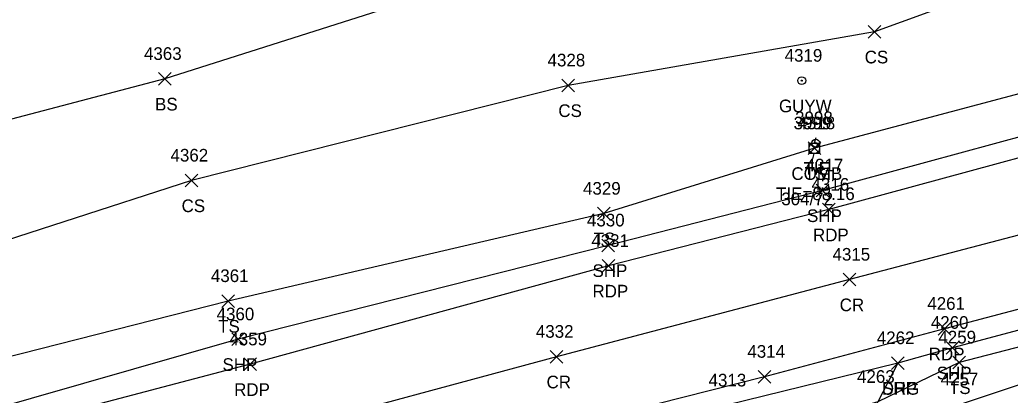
# Model space of a CAD drawing. Extents: x 1520648 to 1523413, y 732854 to 735518.
# Drawn here: x 1520739.3 to 1520895.7, y 733427.6 to 733487 of the extents above; entities that cross this region are included whole.
import ezdxf

# ---------------------------------------------------------------- set-up
doc = ezdxf.new("R2010")
doc.units = 0
for name, color, linetype in [('C_A', 7, 'Continuous'), ('C_C', 7, 'Continuous'), ('C_I', 7, 'Continuous'), ('CBP', 7, 'Continuous'), ('L_A', 7, 'Continuous'), ('L_I', 7, 'Continuous'), ('L_TIC', 7, 'Continuous'), ('LELB', 7, 'Continuous'), ('P_A', 7, 'Continuous'), ('P_I', 7, 'Continuous'), ('P_TIC', 7, 'Continuous'), ('PET', 7, 'Continuous'), ('PRC', 7, 'Continuous'), ('PSP', 7, 'Continuous'), ('R_A', 7, 'Continuous'), ('R_I', 7, 'Continuous'), ('R_TIC', 7, 'Continuous'), ('RDG', 7, 'Continuous'), ('U_A', 7, 'Continuous'), ('U_C', 7, 'Continuous'), ('U_I', 7, 'Continuous'), ('UP', 7, 'Continuous'), ('UPGW', 7, 'Continuous')]:
    doc.layers.add(name, color=color, linetype=linetype)

msp = doc.modelspace()

# ---------------------------------------------------------------- linework, layer by layer
at = {"layer": 'CBP'}
for radius in [0.625, 0.0833]:
    msp.add_circle((1520864.99, 733467.49), radius, dxfattribs=at)
at = {"layer": 'L_TIC'}
for points in [[(1520873.27, 733484.11), (1520875.27, 733486.11)], [(1520875.27, 733484.11), (1520873.27, 733486.11)], [(1520761.19, 733476.66), (1520763.19, 733478.66)], [(1520763.19, 733476.66), (1520761.19, 733478.66)], [(1520824.89, 733475.63), (1520826.89, 733477.63)], [(1520826.89, 733475.63), (1520824.89, 733477.63)], [(1520863.8, 733465.7), (1520865.8, 733467.7)], [(1520865.8, 733465.7), (1520863.8, 733467.7)], [(1520765.38, 733460.59), (1520767.38, 733462.59)], [(1520767.38, 733460.59), (1520765.38, 733462.59)], [(1520830.5, 733455.35), (1520832.5, 733457.35)], [(1520832.5, 733455.35), (1520830.5, 733457.35)], [(1520771.19, 733441.53), (1520773.19, 733443.53)], [(1520773.19, 733441.53), (1520771.19, 733443.53)], [(1520886.62, 733431.82), (1520888.62, 733433.82)], [(1520888.62, 733431.82), (1520886.62, 733433.82)]]:
    msp.add_lwpolyline(points, dxfattribs=at)
at = {"layer": 'LELB'}
for points in [[(1520933.58, 733575.42), (1520942.19, 733540.15), (1520944.3, 733517.3), (1520942.35, 733502.31), (1520935.92, 733493.43), (1520920.42, 733481.51), (1520864.8, 733466.7), (1520831.5, 733456.35), (1520772.19, 733442.53), (1520730.55, 733431.91), (1520670.98, 733415.63)], [(1520924.94, 733571.69), (1520931.25, 733539.14), (1520932.11, 733517.28), (1520920.03, 733501.75), (1520874.27, 733485.11), (1520825.89, 733476.63), (1520766.38, 733461.59), (1520726.01, 733448.53), (1520664.21, 733429.23)], [(1520912.95, 733567.21), (1520918.33, 733540.81), (1520912.15, 733526.62), (1520872.04, 733499.31), (1520820.67, 733496.33), (1520762.19, 733477.66), (1520720.67, 733466.78), (1520660.6, 733449.58)], [(1521084, 733484.54), (1521067.58, 733479.07), (1521049.77, 733473.83), (1520986.71, 733459.8), (1520946.37, 733448.2), (1520906.56, 733437.71), (1520887.62, 733432.82), (1520874.82, 733426.59), (1520851.23, 733419.6), (1520833.59, 733418.06), (1520824.1, 733415.79), (1520817.47, 733414.55), (1520789.23, 733404.3), (1520782.06, 733399.14), (1520771.54, 733396.06), (1520749.1, 733390.85), (1520744.37, 733386.94), (1520745.44, 733378.48), (1520749.8, 733369.39), (1520752.39, 733361.75), (1520762.08, 733336.81), (1520765.3, 733336.98)], [(1521038.84, 733468.84), (1520987.4, 733455.86), (1520949.31, 733443.39), (1520907.36, 733432.7), (1520887.97, 733426.2), (1520871.27, 733419.86), (1520861.99, 733407.36), (1520847.71, 733403.77), (1520838.35, 733404.94), (1520822.18, 733406.09), (1520819.36, 733394.56), (1520817.03, 733387.06)]]:
    msp.add_lwpolyline(points, dxfattribs=at)
at = {"layer": 'P_TIC'}
for points in [[(1520865.08, 733459.02), (1520867.08, 733461.02)], [(1520867.08, 733459.02), (1520865.08, 733461.02)], [(1520866.06, 733455.98), (1520868.06, 733457.98)], [(1520868.06, 733455.98), (1520866.06, 733457.98)], [(1520831.2, 733450.33), (1520833.2, 733452.33)], [(1520833.2, 733450.33), (1520831.2, 733452.33)], [(1520831.23, 733447.09), (1520833.23, 733449.09)], [(1520833.23, 733447.09), (1520831.23, 733449.09)], [(1520869.34, 733444.92), (1520871.34, 733446.92)], [(1520871.34, 733444.92), (1520869.34, 733446.92)], [(1520884.35, 733437.14), (1520886.35, 733439.14)], [(1520886.35, 733437.14), (1520884.35, 733439.14)], [(1520772.75, 733435.48), (1520774.75, 733437.48)], [(1520774.75, 733435.48), (1520772.75, 733437.48)], [(1520885.57, 733434.14), (1520887.57, 733436.14)], [(1520887.57, 733434.14), (1520885.57, 733436.14)], [(1520823.04, 733432.72), (1520825.04, 733434.72)], [(1520825.04, 733432.72), (1520823.04, 733434.72)], [(1520774.63, 733431.52), (1520776.63, 733433.52)], [(1520776.63, 733431.52), (1520774.63, 733433.52)], [(1520876.93, 733431.71), (1520878.93, 733433.71)], [(1520878.93, 733431.71), (1520876.93, 733433.71)], [(1520855.88, 733429.56), (1520857.88, 733431.56)], [(1520857.88, 733429.56), (1520855.88, 733431.56)]]:
    msp.add_lwpolyline(points, dxfattribs=at)
at = {"layer": 'PET'}
for points in [[(1521359.51, 733585.39), (1521298.08, 733569.34), (1521228.86, 733551.45), (1521196.2, 733542.53), (1521147.39, 733530.28), (1521096.51, 733517.17), (1521058.61, 733507.66), (1520970.9, 733484.81), (1520924.79, 733472.7), (1520867.06, 733456.98), (1520832.23, 733448.09), (1520775.63, 733432.52), (1520733.45, 733421.44), (1520673.24, 733405.46)], [(1521365.83, 733563.19), (1521305.64, 733547.24), (1521243.51, 733531.59), (1521203.56, 733520.88), (1521152.14, 733507.85), (1521105.31, 733495.85), (1521097.86, 733494.19), (1521063.42, 733485.34), (1521018.35, 733473.43), (1520975.95, 733462.3), (1520931.61, 733450.37), (1520885.35, 733438.14), (1520856.88, 733430.56), (1520818.39, 733420.77), (1520780.83, 733410.61), (1520744.81, 733401.09), (1520678.56, 733383.16)]]:
    msp.add_lwpolyline(points, dxfattribs=at)
at = {"layer": 'PRC'}
msp.add_lwpolyline([(1521363.3, 733574.52), (1521301.52, 733558.53), (1521239.8, 733542.16), (1521200.1, 733531.63), (1521149.34, 733518.97), (1521098.13, 733505.5), (1521061.28, 733496.8), (1521014.81, 733484.07), (1520973.92, 733473.61), (1520928.9, 733461.35), (1520870.34, 733445.92), (1520824.04, 733433.72), (1520778.39, 733421.36), (1520737.02, 733410.36), (1520676.97, 733394.51)], dxfattribs=at)
at = {"layer": 'PSP'}
for points in [[(1521358.34, 733588.53), (1521296.5, 733572.12), (1521227.74, 733554.37), (1521195.21, 733545.64), (1521147.51, 733533.73), (1521095.86, 733520.25), (1521076.01, 733514.97), (1521056.93, 733511.88), (1521033.51, 733506.4), (1520966.21, 733488.2), (1520925.69, 733476.27), (1520866.08, 733460.02), (1520832.2, 733451.33), (1520773.75, 733436.48), (1520732.76, 733424.74), (1520671.96, 733408.83)], [(1521366.85, 733559.74), (1521307.16, 733544.25), (1521244.3, 733528.24), (1521204.94, 733517.79), (1521152.82, 733504.37), (1521106.57, 733492.89), (1521080.1, 733485.88), (1521063.46, 733481.98), (1521018.86, 733470.55), (1520976.52, 733459.1), (1520931.66, 733447.13), (1520886.57, 733435.14), (1520877.93, 733432.71), (1520850.75, 733426.02), (1520817.82, 733417.13), (1520781.5, 733407.41), (1520747.69, 733397.94), (1520743.14, 733395.11), (1520720.82, 733389.47), (1520716.87, 733390.02), (1520705.4, 733386.95), (1520679.31, 733380.34)]]:
    msp.add_lwpolyline(points, dxfattribs=at)
at = {"layer": 'R_TIC'}
for points in [[(1520876.93, 733431.71), (1520878.93, 733433.71)], [(1520878.93, 733431.71), (1520876.93, 733433.71)]]:
    msp.add_lwpolyline(points, dxfattribs=at)
at = {"layer": 'RDG'}
msp.add_lwpolyline([(1520877.93, 733432.71), (1520874.82, 733426.59), (1520871.27, 733419.86), (1520872.04, 733411.55), (1520882.83, 733406.82), (1520886.47, 733392.68), (1520888.14, 733371.18), (1520869.05, 733363.96), (1520863.07, 733360.43), (1520863.54, 733349.73)], dxfattribs=at)
at = {"layer": 'UP'}
for p, q in [((1520863.93, 733465.84), (1520863.93, 733467.51)), ((1520863.93, 733467.51), (1520865.6, 733467.51)), ((1520865.01, 733468.34), (1520864.76, 733467.51)), ((1520865.6, 733467.51), (1520865.6, 733465.84)), ((1520865.6, 733465.84), (1520863.93, 733465.84)), ((1520864.51, 733465.01), (1520864.76, 733465.84)), ((1520864.76, 733466.68), (1520864.76, 733466.68))]:
    msp.add_line(p, q, dxfattribs=at)
msp.add_circle((1520864.76, 733466.68), 0.833, dxfattribs=at)
at = {"layer": 'UPGW'}
for radius in [0.625, 0.0833]:
    msp.add_circle((1520862.78, 733477.38), radius, dxfattribs=at)

# ---------------------------------------------------------------- texts
at = {"layer": 'C_A'}
msp.add_text('TIE', height=2, dxfattribs=at).set_placement((1520863.07, 733462.49))
at = {"layer": 'C_C'}
msp.add_text('TIE=88.16', height=2, dxfattribs=at).set_placement((1520858.73, 733458.49))
at = {"layer": 'C_I'}
msp.add_text('3998', height=2, dxfattribs=at).set_placement((1520861.73, 733470.49))
at = {"layer": 'L_A'}
for s, p in [('CS', (1520872.72, 733480.11)), ('BS', (1520760.63, 733472.66)), ('CS', (1520824.33, 733471.63)), ('TS', (1520863.21, 733461.7)), ('CS', (1520764.82, 733456.59)), ('TS', (1520829.91, 733451.35)), ('TS', (1520770.6, 733437.53)), ('TS', (1520886.03, 733427.82))]:
    msp.add_text(s, height=2, dxfattribs=at).set_placement(p)
at = {"layer": 'L_I'}
for s, p in [('4363', (1520758.88, 733480.66)), ('4328', (1520822.63, 733479.63)), ('4318', (1520862.11, 733469.7)), ('4362', (1520763.07, 733464.59)), ('4329', (1520828.23, 733459.35)), ('4361', (1520769.45, 733445.53)), ('4259', (1520884.36, 733435.82)), ('4263', (1520871.51, 733429.59)), ('4257', (1520884.72, 733429.2))]:
    msp.add_text(s, height=2, dxfattribs=at).set_placement(p)
at = {"layer": 'P_A'}
for s, p in [('SHP', (1520863.61, 733455.02)), ('RDP', (1520864.55, 733451.98)), ('SHP', (1520829.73, 733446.33)), ('RDP', (1520829.72, 733443.09)), ('CR', (1520868.77, 733440.92)), ('RDP', (1520882.84, 733433.14)), ('SHP', (1520771.28, 733431.48)), ('SHP', (1520884.1, 733430.14)), ('CR', (1520822.47, 733428.72)), ('RDP', (1520773.12, 733427.52)), ('SHP', (1520875.47, 733427.71))]:
    msp.add_text(s, height=2, dxfattribs=at).set_placement(p)
at = {"layer": 'P_I'}
for s, p in [('4317', (1520863.39, 733463.02)), ('4316', (1520864.32, 733459.98)), ('4330', (1520828.85, 733454.33)), ('4331', (1520829.54, 733451.09)), ('4315', (1520867.64, 733448.92)), ('4261', (1520882.61, 733441.14)), ('4360', (1520770.35, 733439.48)), ('4260', (1520883.17, 733438.14)), ('4332', (1520820.78, 733436.72)), ('4262', (1520874.63, 733435.71)), ('4359', (1520772.36, 733435.52)), ('4314', (1520854.19, 733433.56)), ('4313', (1520848.06, 733429.02))]:
    msp.add_text(s, height=2, dxfattribs=at).set_placement(p)
at = {"layer": 'R_A'}
msp.add_text('DRG', height=2, dxfattribs=at).set_placement((1520875.42, 733427.71))
at = {"layer": 'R_I'}
for s, p in [('4262', (1520874.63, 733435.71)), ('4263', (1520871.51, 733429.59))]:
    msp.add_text(s, height=2, dxfattribs=at).set_placement(p)
at = {"layer": 'U_A'}
for s, p in [('GUYW', (1520859.18, 733472.38)), ('COMB', (1520861.15, 733461.68))]:
    msp.add_text(s, height=2, dxfattribs=at).set_placement(p)
at = {"layer": 'U_C'}
msp.add_text('304/72', height=2, dxfattribs=at).set_placement((1520859.55, 733457.68))
at = {"layer": 'U_I'}
for s, p in [('4319', (1520860.08, 733480.38)), ('3999', (1520861.49, 733469.68))]:
    msp.add_text(s, height=2, dxfattribs=at).set_placement(p)

doc.saveas('drawing.dxf')
